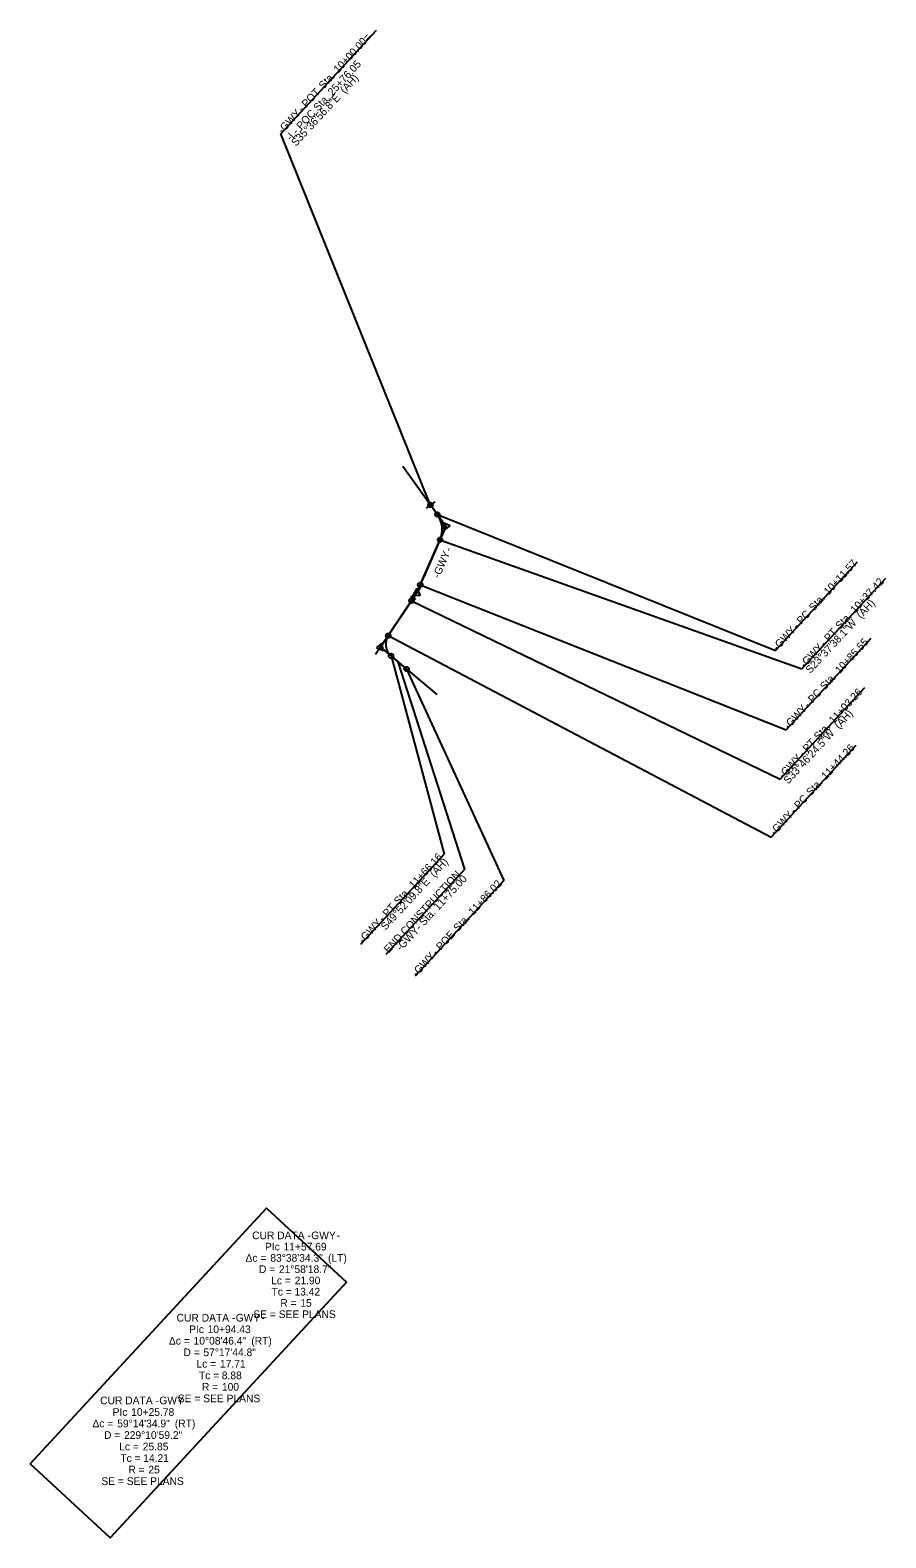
# Model space of a CAD drawing. Extents: x 1768840 to 1770587, y 999488 to 1004795.
import ezdxf

# ---------------------------------------------------------------- set-up
doc = ezdxf.new("R2010")
doc.units = 0
for name, color, linetype in [('Default', 7, 'Continuous'), ('Exist DTM Drainline', 7, 'Continuous'), ('Exist Property Iron Pin CELL', 7, 'Continuous'), ('Exist Property Text', 7, 'Continuous'), ('Exist Structure Minor Drop Inlet', 7, 'Continuous'), ('Exist Structure Minor Paved Ditch or Gutter', 7, 'Continuous'), ('Exist Structure Minor Pipes RCP 24 Inch', 7, 'Continuous'), ('Exist Utilities Sanitary Sewer Manhole CELL', 7, 'Continuous'), ('Exist Utilities Telephone Pole CELL', 7, 'Continuous')]:
    doc.layers.add(name, color=color, linetype=linetype)

msp = doc.modelspace()

# ---------------------------------------------------------------- linework, layer by layer
at = {"layer": 'Default'}
for p, q in [((1769246.1, 1000475.9), (1769204.2, 1000534.5)), ((1769246.1, 1000475.9), (1769217.2, 1000410)), ((1769217.5, 1000410.7), (1769246.4, 1000476.6)), ((1769246.1, 1000475.9), (1769246.1, 1000475.9)), ((1769182.3, 1000358), (1769222.4, 1000417.9)), ((1769217.5, 1000410.7), (1769177.5, 1000350.8)), ((1769217.5, 1000410.7), (1769217.5, 1000410.7)), ((1769182.3, 1000358), (1769237.4, 1000311.6)), ((1769182.3, 1000358), (1769182.3, 1000358))]:
    msp.add_line(p, q, dxfattribs=at)
for points in [[(1769250.2, 1000476.4), (1769243.6, 1000479.3), (1769244.4, 1000472.1)], [(1769221.2, 1000408.7), (1769217.4, 1000414.8), (1769214, 1000408.5)], [(1769178.2, 1000357.5), (1769184.9, 1000354.8), (1769183.9, 1000361.9)]]:
    msp.add_lwpolyline(points, close=True, dxfattribs=at)
at = {"layer": 'Exist Property Iron Pin CELL'}
msp.add_line((1769216.7, 1000404.6), (1769212, 1000407.5), dxfattribs=at)
at = {"layer": 'Exist Property Text'}
msp.add_line((1769235.4, 1000500), (1769226.8, 1000493.8), dxfattribs=at)
at = {"layer": 'Exist Structure Minor Drop Inlet'}
msp.add_lwpolyline([(1768839.9, 999560.4), (1769070.8, 999810.2), (1769149.1, 999737.9), (1768918.1, 999488.1)], close=True, dxfattribs=at)
at = {"layer": 'Exist Structure Minor Paved Ditch or Gutter'}
for p, q in [((1769084.8, 1000859.2), (1769178.5, 1000960.6)), ((1769230.3, 1000499), (1769084.8, 1000859.2)), ((1769237.8, 1000487.5), (1769568.3, 1000354.7)), ((1769240.4, 1000462.9), (1769594, 1000336.9)), ((1769568.3, 1000354.7), (1769648.3, 1000441.2)), ((1769221.1, 1000418.8), (1769578.8, 1000277.2)), ((1769594, 1000336.9), (1769676.1, 1000425.4)), ((1769212.6, 1000403.3), (1769572.7, 1000229)), ((1769189.8, 1000369.2), (1769564.1, 1000172.5)), ((1769578.8, 1000277.2), (1769661.7, 1000366.9)), ((1769192.6, 1000349.4), (1769244.4, 1000155.9)), ((1769264.6, 1000141.2), (1769199.4, 1000343.7)), ((1769207.8, 1000336.6), (1769302.7, 1000130.1)), ((1769572.7, 1000229), (1769655.6, 1000318.6)), ((1769564.1, 1000172.5), (1769647, 1000262.2)), ((1769244.4, 1000155.9), (1769162.7, 1000067.5)), ((1769264.6, 1000141.2), (1769187.6, 1000057.9)), ((1769302.7, 1000130.1), (1769216.3, 1000036.6))]:
    msp.add_line(p, q, dxfattribs=at)
for centre in [(1769231.1, 1000496.9), (1769237.8, 1000487.5), (1769240.4, 1000462.9), (1769221.1, 1000418.8), (1769212.6, 1000403.3), (1769189.8, 1000369.2), (1769192.6, 1000349.4), (1769207.8, 1000336.6)]:
    msp.add_circle(centre, 2.25, dxfattribs=at)
at = {"layer": 'Exist Structure Minor Pipes RCP 24 Inch'}
for p, q in [((1769245.7, 1000476.5), (1769231.1, 1000496.9)), ((1769236.9, 1000454.9), (1769224.3, 1000426.1)), ((1769208.2, 1000396.7), (1769192.4, 1000373.1)), ((1769207.8, 1000336.6), (1769192.6, 1000349.4))]:
    msp.add_line(p, q, dxfattribs=at)
for centre, radius, start, end in [((1769217.5, 1000472.9), 25, 336.3727, 35.6158), ((1769129.5, 1000458.9), 100, 326.2265, 336.3727), ((1769202.3, 1000360.9), 15, 146.2265, 229.8694)]:
    msp.add_arc(centre, radius, start, end, dxfattribs=at)
at = {"layer": 'Exist Utilities Sanitary Sewer Manhole CELL'}
for p, q in [((1769231.1, 1000496.9), (1769237.8, 1000487.5)), ((1769240.4, 1000462.9), (1769221.1, 1000418.8)), ((1769212.6, 1000403.3), (1769189.8, 1000369.2)), ((1769192.6, 1000349.4), (1769207.8, 1000336.6))]:
    msp.add_line(p, q, dxfattribs=at)
for centre, radius, start, end in [((1769217.5, 1000472.9), 25, 336.3727, 35.6158), ((1769129.5, 1000458.9), 100, 326.2265, 336.3727), ((1769202.3, 1000360.9), 15, 146.2265, 229.8694)]:
    msp.add_arc(centre, radius, start, end, dxfattribs=at)
at = {"layer": 'Exist Utilities Telephone Pole CELL'}
for centre in [(1769237.8, 1000487.5), (1769237.8, 1000487.5), (1769192.6, 1000349.4), (1769200.2, 1000343)]:
    msp.add_circle(centre, 0.05, dxfattribs=at)

# ---------------------------------------------------------------- texts
at = {"layer": 'Exist DTM Drainline'}
for s, rotation, p in [(' (AH)', 47.2512, (1769145.5, 1000896.2)), ('S35°36\'56.8"E', 47.2512, (1769099.7, 1000846.6)), ('GWY', 66.3459, (1769240.9, 1000427.8)), ('-', 66.3459, (1769250.9, 1000450.7)), ('-', 66.3459, (1769239.5, 1000424.6)), (' (AH)', 47.1224, (1769650.2, 1000383.3)), ('S23°37\'38.1"W', 47.1224, (1769602.2, 1000331.7)), (' (AH)', 47.2512, (1769628.6, 1000275.5)), ('S33°46\'24.5"W', 47.2512, (1769580.7, 1000223.7)), (' (AH)', 47.2512, (1769233.1, 1000130.6)), ('S49°52\'09.8"E', 47.2512, (1769187.2, 1000080.9)), ('-GWY- Sta. 11+75.00', 47.2512, (1769202.1, 1000060.6))]:
    msp.add_text(s, height=7.5, rotation=rotation, dxfattribs=at).set_placement(p)
at = {"layer": 'Exist Structure Minor Drop Inlet'}
for s, p in [('CUR DATA -', (1769056.8, 999779.7)), ('GWY', (1769114.6, 999779.7)), ('-', (1769139.6, 999779.7)), ('Δc = ', (1769050.4, 999757.7)), ('PIc ', (1769069.4, 999768.7)), ('83°38\'34.3"', (1769074.6, 999757.7)), ('11+57.69', (1769087.5, 999768.7)), (' (LT)', (1769128.2, 999757.7)), ('D = ', (1769063.5, 999746.7)), ('21°58\'18.7"', (1769083, 999746.7)), ('Lc = ', (1769075.4, 999735.7)), ('21.90', (1769098.4, 999735.7)), ('Tc = ', (1769075.8, 999724.7)), ('R = ', (1769084.4, 999713.7)), ('13.42', (1769098.2, 999724.7)), ('15', (1769103.9, 999713.7)), ('CUR DATA -', (1768983, 999699.3)), ('GWY', (1769040.8, 999699.3)), ('SE = SEE PLANS', (1769058, 999702.7)), ('PIc ', (1768995.2, 999688)), ('10+94.43', (1769013.3, 999688)), ('-', (1769065.9, 999699.3)), ('Δc = ', (1768975.5, 999676.8)), ('10°08\'46.4"', (1768999.6, 999676.8)), (' (RT)', (1769053.2, 999676.8)), ('D = ', (1768989.7, 999665.5)), ('Lc = ', (1769002.4, 999654.3)), ('57°17\'44.8"', (1769009.2, 999665.5)), ('17.71', (1769025.4, 999654.3)), ('Tc = ', (1769004.8, 999643)), ('8.88', (1769027.2, 999643)), ('R = ', (1769007.8, 999631.8)), ('100', (1769027.3, 999631.8)), ('CUR DATA -', (1768908.3, 999618.5)), ('GWY', (1768966.1, 999618.5)), ('SE = SEE PLANS', (1768984.2, 999620.5)), ('-', (1768991.2, 999618.5)), ('Δc = ', (1768900.8, 999596)), ('PIc ', (1768920.5, 999607.2)), ('59°14\'34.9"', (1768925, 999596)), ('10+25.78', (1768938.6, 999607.2)), (' (RT)', (1768978.5, 999596)), ('D = ', (1768912.1, 999584.7)), ('229°10\'59.2"', (1768931.6, 999584.7)), ('Lc = ', (1768926.9, 999573.5)), ('25.85', (1768949.9, 999573.5)), ('Tc = ', (1768928, 999562.2)), ('R = ', (1768935.9, 999551)), ('14.21', (1768950.4, 999562.2)), ('25', (1768955.4, 999551)), ('SE = SEE PLANS', (1768909.5, 999539.7))]:
    msp.add_text(s, height=7.5, dxfattribs=at).set_placement(p)
at = {"layer": 'Exist Structure Minor Paved Ditch or Gutter'}
for s, rotation, p in [('10+00.00=', 47.2512, (1769141.1, 1000918.2)), ('-L- POC Sta. 25+76.05 ', 47.2512, (1769094.5, 1000851.8)), ('Sta. ', 47.2512, (1769126.5, 1000902.4)), ('- POT ', 47.2512, (1769105.7, 1000879.9)), ('GWY', 47.2512, (1769088.7, 1000861.5)), ('-', 47.2512, (1769086.3, 1000858.9)), ('10+11.57', 47.2512, (1769620.1, 1000408.3)), ('10+37.42', 47.1224, (1769646.1, 1000390.5)), ('Sta. ', 47.2512, (1769605.5, 1000392.5)), ('PC', 47.2512, (1769593.6, 1000379.7)), ('Sta. ', 47.1224, (1769631.4, 1000374.7)), ('GWY', 47.2512, (1769572.3, 1000356.6)), ('- ', 47.2512, (1769589.3, 1000375)), ('PT', 47.1224, (1769620.4, 1000362.8)), ('-', 47.2512, (1769569.9, 1000354)), ('GWY', 47.1224, (1769599, 1000339.8)), ('- ', 47.1224, (1769616, 1000358.1)), ('10+85.55', 47.2512, (1769631.1, 1000331.5)), ('-', 47.1224, (1769596.6, 1000337.2)), (' Sta. ', 47.2512, (1769614.5, 1000313.5)), ('PC', 47.2512, (1769604.6, 1000302.9)), ('11+03.26', 47.2512, (1769625.1, 1000282.6)), ('GWY', 47.2512, (1769583.3, 1000279.8)), ('- ', 47.2512, (1769600.3, 1000298.2)), ('-', 47.2512, (1769580.9, 1000277.2)), (' Sta. ', 47.2512, (1769608.5, 1000264.6)), ('PT', 47.2512, (1769599.4, 1000254.8)), ('GWY', 47.2512, (1769578.1, 1000231.7)), ('- ', 47.2512, (1769595.1, 1000250.1)), ('11+44.26', 47.2512, (1769617.6, 1000228.1)), ('-', 47.2512, (1769575.7, 1000229.2)), (' Sta. ', 47.2512, (1769601, 1000210.1)), ('PC', 47.2512, (1769591.1, 1000199.4)), ('GWY', 47.2512, (1769569.8, 1000176.3)), ('- ', 47.2512, (1769586.8, 1000194.7)), ('-', 47.2512, (1769567.4, 1000173.8)), ('11+66.16', 47.2512, (1769214.7, 1000121.6)), ('END CONSTRUCTION', 47.2512, (1769190.2, 1000058.5)), (' Sta. ', 47.2512, (1769198.1, 1000103.7)), ('11+86.02', 47.2512, (1769272.8, 1000095.5)), ('PT', 47.2512, (1769189, 1000093.8)), ('GWY', 47.2512, (1769167.7, 1000070.8)), ('- ', 47.2512, (1769184.7, 1000089.1)), (' Sta. ', 47.2512, (1769256.2, 1000077.5)), ('POE', 47.2512, (1769241.2, 1000061.3)), ('-', 47.2512, (1769165.3, 1000068.2)), ('GWY', 47.2512, (1769219.8, 1000038.2)), ('- ', 47.2512, (1769236.8, 1000056.6)), ('-', 47.2512, (1769217.5, 1000035.6))]:
    msp.add_text(s, height=7.5, rotation=rotation, dxfattribs=at).set_placement(p)

doc.saveas('drawing.dxf')
